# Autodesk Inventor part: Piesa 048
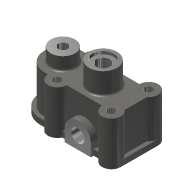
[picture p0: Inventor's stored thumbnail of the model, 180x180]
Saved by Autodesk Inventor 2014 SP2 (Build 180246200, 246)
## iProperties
Created: 2009-01
Part Number: Piesa 048
Document SubType Name: Modeling
Designer: Costel
Material: Steel, Cast
Density: 7.85 g/cm^3
Appearance: Steel - Cast
Mass: 7689.62 g
Surface Area: 1825.12 cm^2
Volume: 979.57 cm^3
Author: Costel
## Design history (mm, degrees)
sketch "Sketch1"
  geometry: L1 (-69.525, 0)-(231.827, 0) reference; L2 (0, -76.294)-(0, 101.725) reference; L3 (164, -40)-(164, 40); L4 (0, 48)-(9.67, 48); L5 (46.33, 48)-(125.67, 48); L6 (0, -48)-(9.67, -48); L7 (46.33, -48)-(125.67, -48); A1 r 48 centre (0, 0) between (0, 48) and (0, -48); A2 r 20 centre (144, 40) between (164, 40) and (125.67, 48); A3 r 20 centre (144, -40) between (125.67, -48) and (164, -40); A4 r 20 centre (28, 40) between (46.33, 48) and (9.67, 48); A5 r 20 centre (28, -40) between (9.67, -48) and (46.33, -48)
  constraints: 10 end point, 10 point on circle, 6 perpendicular, 5 centre point, 5 tangent, 2 point on line, 2 symmetric about line, 1 equal radius, 1 horizontal alignment, 2 other
  dimensions: "d2" = 80 distance of A3.centre A2.centre; "d3" = 144 horizontal distance of A1.centre A3.centre; "d4" = 28 distance from line of L2 A4.centre; "d5" = 48 radius of A1; "d6" = 20 radius of A2
extrude "Extrusion1" new body sketch "Sketch1" distance "d7" = 12; taper "d8" = 0 deg
sketch "Sketch2"
  geometry: L1 (156, -24)-(156, 24); L2 (0, -72)-(0, 96) reference; L3 (0, -40)-(8, -40); L4 (48, -40)-(124, -40); L5 (124, 40)-(48, 40); L6 (8, 40)-(0, 40); L7 (164, 40)-(164, -40) reference; A1 r 48 centre (0, 0) between (0, 48) and (0, -48) reference; A2 r 20 centre (144, -40) between (125.67, -48) and (164, -40) reference; A3 r 20 centre (144, -40) between (124, -40) and (156, -24); A4 r 40 centre (0, 0) between (0, 40) and (0, -40); A5 r 20 centre (28, -40) between (9.67, -48) and (46.33, -48) reference; A6 r 20 centre (28, 40) between (46.33, 48) and (9.67, 48) reference; A7 r 20 centre (144, 40) between (164, 40) and (125.67, 48) reference; A8 r 20 centre (28, -40) between (8, -40) and (48, -40); A9 r 20 centre (28, 40) between (48, 40) and (8, 40); A10 r 20 centre (144, 40) between (156, 24) and (124, 40)
  constraints: 15 point on circle, 10 end point, 5 centre point, 5 coincident, 4 parallel, 2 collinear, 2 perpendicular, 2 point on line, 1 equal radius
  dimensions: "d9" = 8 distance between parallel lines of L7 L1; "d12" = 40 radius of A4; "d13" = 20 radius of A3
extrude "Extrusion2" join sketch "Sketch2" distance "d14" = 82; taper "d15" = 0 deg
sketch "Sketch3"
  geometry: L1 (-125.67, 48)-(-46.33, 48) reference; L2 (-164, -40)-(-164, 40) reference; L3 (0, -48)-(-9.67, -48) reference; L4 (-146, -20.1)-(-146, 20.1); L5 (0, -32)-(-9.67, -32); L6 (-46.33, -32)-(-125.67, -32); L7 (-125.67, 32)-(-46.33, 32); L8 (-9.67, 32)-(0, 32); A1 r 48 centre (0, 0) between (0, -48) and (0, 48) reference; A2 r 20 centre (-28, 40) between (-9.67, 48) and (-46.33, 48) reference; A3 r 20 centre (-144, 40) between (-125.67, 48) and (-164, 40) reference; A4 r 20 centre (-144, -40) between (-164, -40) and (-125.67, -48) reference; A5 r 20 centre (-28, -40) between (-46.33, -48) and (-9.67, -48) reference; A6 r 32 centre (0, 0) between (0, -32) and (0, 32); A7 r 20 centre (-28, 40) between (-46.33, 32) and (-9.67, 32); A8 r 20 centre (-144, 40) between (-146, 20.1) and (-125.67, 32); A9 r 20 centre (-144, -40) between (-125.67, -32) and (-146, -20.1); A10 r 20 centre (-28, -40) between (-9.67, -32) and (-46.33, -32)
  constraints: 13 end point, 13 point on circle, 6 parallel, 5 centre point, 5 coincident, 4 concentric, 2 collinear, 2 perpendicular, 2 point on line, 2 tangent
  dimensions: "d17" = 18 distance between parallel lines of L2 L4; "d18" = 32 radius of A6
extrude "Extrusion3" cut sketch "Sketch3" distance "d21" = 84; taper "d22" = 0 deg
sketch "Sketch4"
  geometry: L1 (0, -72)-(0, 96) reference; L2 (69.2, 0)-(-227.6, 0) reference; C1 r 26 at (-86, 0)
  constraints: 1 centre point, 1 point on line
  dimensions: "d23" = 52 diameter of C1; "d24" = 86 distance from line of L1 C1.centre
extrude "Extrusion4" join sketch "Sketch4" distance "d25" = 12; taper "d26" = 0 deg
sketch "Sketch5"
  geometry: C1 r 26 at (86, 0) reference; C2 r 30 at (86, 0)
  constraints: 1 centre point, 1 coincident
  dimensions: "d28" = 60 diameter of C2
extrude "Extrusion5" join sketch "Sketch5" distance "d29" = 46; taper "d30" = 0 deg
sketch "Sketch6"
  geometry: C1 r 26 at (0, 0); A1 r 40 centre (0, 0) between (0, 40) and (0, -40) reference
  constraints: 1 centre point, 1 coincident
  dimensions: "d31" = 52 diameter of C1
extrude "Extrusion6" join sketch "Sketch6" distance "d32" = 28; taper "d33" = 0 deg
hole "Hole1" diameter "d36" = 20; stored, may be unused: countersink angle "d40" = 90 deg, drill point angle "d42" = 118 deg; dims "d34" = 10, "d35" = 10, "d37" = 6, "d38" = 4, "d39" = 2, "d41" = 8
hole "Hole2" diameter "d45" = 28; stored, may be unused: countersink angle "d49" = 90 deg, drill point angle "d51" = 118 deg; dims "d43" = 10, "d44" = 10, "d46" = 6, "d47" = 46, "d48" = 6, "d50" = 8
sketch "Sketch7"
  geometry: A1 r 20 centre (28, -40) between (8, -40) and (48, -40) reference; A2 r 20 centre (144, -40) between (124, -40) and (156, -24) reference; A3 r 20 centre (144, 40) between (156, 24) and (124, 40) reference; A4 r 20 centre (28, 40) between (48, 40) and (8, 40) reference; 4 further points
  constraints: 4 coincident
hole "Hole3" sketch "Sketch7" at (28, -40), (28, 40), (144, 40), (144, -40) diameter "d52" = 16; stored, may be unused: countersink angle "d56" = 90 deg, drill point angle "d58" = 118 deg; dims "d53" = 6, "d54" = 46, "d55" = 6, "d57" = 8
workaxis "Work Axis1"
workplane "Work Plane1"
sketch "Sketch8"
  geometry: L1 (39.67, -14)-(39.67, 182) reference; L2 (11.67, 26)-(11.67, 0); L3 (67.67, 26)-(67.67, 0); L4 (67.67, 0)-(11.67, 0); L5 (0, 0)-(79.339, 0) reference; A1 r 28 centre (39.67, 26) between (67.67, 26) and (11.67, 26)
  constraints: 6 end point, 2 parallel, 2 point on circle, 2 tangent, 1 centre point, 1 collinear, 1 perpendicular, 1 point on line
  dimensions: "d61" = 28 radius of A1; "d62" = 26 distance from line of L4 A1.centre
extrude "Extrusion7" join sketch "Sketch8" stored distance "d63" = 28; taper "d64" = 0 deg
workplane "Work Plane2"
mirror "Mirror1"
hole "Hole4" diameter "d68" = 28; stored, may be unused: countersink angle "d72" = 90 deg, drill point angle "d74" = 118 deg; dims "d66" = 10, "d67" = 10, "d69" = 6, "d70" = 46, "d71" = 6, "d73" = 8
fillet "Fillet1" dims "d75" = 4
body "Solid1"
other parameters: "d59" = 6, "d65" = 0
